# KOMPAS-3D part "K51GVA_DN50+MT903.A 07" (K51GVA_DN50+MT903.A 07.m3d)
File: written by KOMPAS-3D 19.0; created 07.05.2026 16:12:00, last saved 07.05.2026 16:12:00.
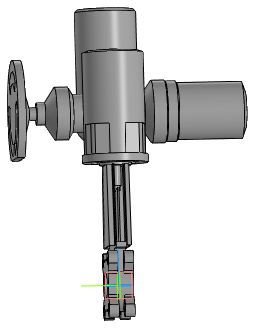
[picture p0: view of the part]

Document properties: Автор: Энергия; Полное имя файла: ..\K51GVA_DN50-DN1000+MT903.A\K51GVA_DN50+MT903.A 07.a3d

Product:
- Part/product: K51GVA_DN50+MT903.A 07
    Масса: 71.9602

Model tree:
1. Операция без истории:1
